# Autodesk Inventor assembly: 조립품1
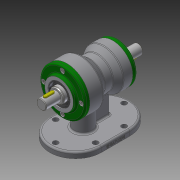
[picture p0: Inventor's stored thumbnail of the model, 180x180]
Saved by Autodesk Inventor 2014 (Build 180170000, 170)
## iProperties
Created: 2020-01
Part Number: 조립품1
Document SubType Name: Assembly
Designer: kh
Author: kh
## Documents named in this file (11)
- D:\700104V1024\조립품1.iam
- D:\700104V1024\본체.ipt
- D:\700104V1024\Ű 5 x 5 x 18.ipt
- D:\700104V1024\베어링 6203.ipt
- D:\700104V1024\축.ipt
- D:\700104V1024\앞커버.ipt
- D:\700104V1024\뒤커버.ipt
- D:\700104V1024\베어링 6205.ipt
- D:\700104V1024\볼트 M4.ipt
- D:\700104V1024\오일 실 25 38 8.ipt
- D:\700104V1024\오일 실 17 30 8.ipt
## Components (2 placed, 1 different names)
1. Ű 5 x 5 x 18:1 — 각도:1
2. Ű 5 x 5 x 18:2
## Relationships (1: Angle 1)
- 각도:1 [Angle]: Ű 5 x 5 x 18:1
